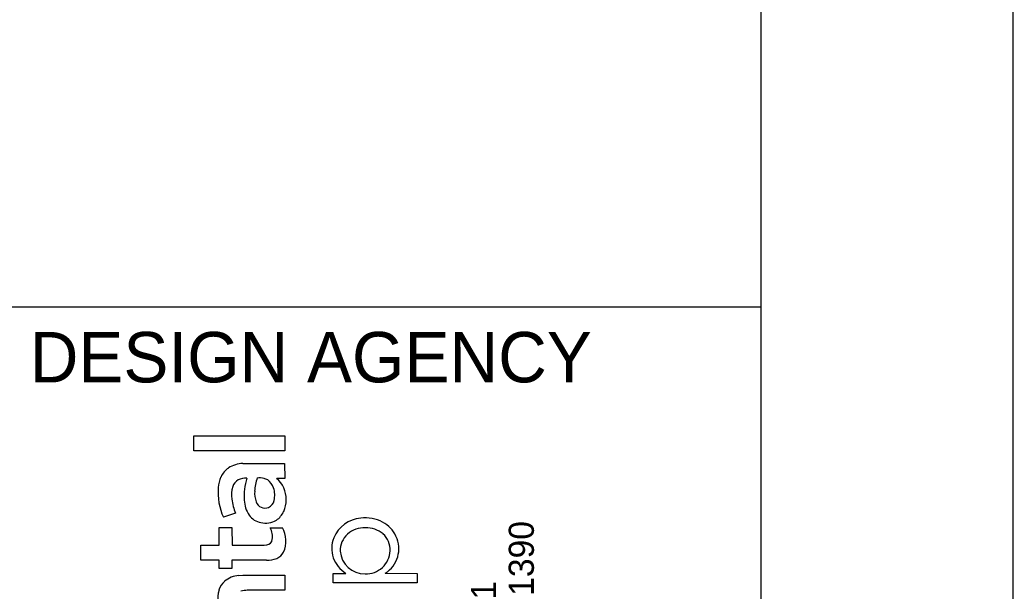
# Model space of a CAD drawing. Extents: x 0 to 63.6, y 0 to 22.
# Drawn here: x 32.03 to 34, y 4.436 to 5.569 of the extents above; entities that cross this region are included whole.
import ezdxf

# ---------------------------------------------------------------- set-up
doc = ezdxf.new("R2010")
doc.units = 0
for name, color, linetype in [('SH_Border', 7, 'Continuous'), ('SH_Cut_Line', 7, 'Continuous'), ('SH_Data', 7, 'Continuous')]:
    doc.layers.add(name, color=color, linetype=linetype)

msp = doc.modelspace()

# ---------------------------------------------------------------- linework, layer by layer
at = {"layer": 'SH_Border'}
msp.add_line((32, 5), (33.5, 5), dxfattribs=at)
msp.add_lwpolyline([(1.5, 21.5), (33.5, 21.5), (33.5, 0.5), (1.5, 0.5)], close=True, dxfattribs=at)
at = {"layer": 'SH_Cut_Line'}
msp.add_lwpolyline([(0, 0), (34, 0), (34, 22), (0, 22)], close=True, dxfattribs=at)
at = {"layer": 'SH_Data'}
for p, q in [((32.3756, 4.7141), (32.3756, 4.744)), ((32.3756, 4.744), (32.5557, 4.744)), ((32.5557, 4.744), (32.5557, 4.7141)), ((32.5557, 4.7141), (32.3756, 4.7141)), ((32.4727, 4.689), (32.5555, 4.6892)), ((32.5555, 4.6892), (32.5557, 4.6596)), ((32.5557, 4.6596), (32.5397, 4.6596)), ((32.4582, 4.5904), (32.4343, 4.5823)), ((32.4254, 4.527), (32.4255, 4.5621)), ((32.4255, 4.5621), (32.4511, 4.5621)), ((32.4511, 4.5621), (32.4512, 4.527)), ((32.527, 4.5616), (32.5511, 4.5616)), ((32.3896, 4.4972), (32.3896, 4.527)), ((32.3896, 4.527), (32.4254, 4.527)), ((32.4512, 4.527), (32.515, 4.527)), ((32.515, 4.527), (32.52, 4.5275)), ((32.4254, 4.4972), (32.3896, 4.4972)), ((32.4254, 4.4807), (32.4254, 4.4972)), ((32.5197, 4.4972), (32.4511, 4.4972)), ((32.4511, 4.4972), (32.4511, 4.4807)), ((32.4511, 4.4807), (32.4254, 4.4807)), ((32.6515, 4.4521), (32.6515, 4.4711)), ((32.6515, 4.4711), (32.6771, 4.4711)), ((32.7549, 4.4713), (32.8186, 4.4711)), ((32.8186, 4.4711), (32.8184, 4.4521)), ((32.4644, 4.4669), (32.4729, 4.4673)), ((32.4729, 4.4673), (32.5557, 4.4673)), ((32.5557, 4.4673), (32.5557, 4.4375)), ((32.8184, 4.4521), (32.6515, 4.4521)), ((32.5557, 4.4375), (32.4814, 4.4375))]:
    msp.add_line(p, q, dxfattribs=at)
msp.add_lwpolyline([(32.3756, 4.7141), (32.3756, 4.744), (32.5557, 4.744), (32.5557, 4.7141)], close=True, dxfattribs=at)
for points in [[(32.4727, 4.689), (32.5555, 4.6892), (32.5557, 4.6596)], [(32.5557, 4.6596), (32.5397, 4.6596)], [(32.4582, 4.5904), (32.4343, 4.5823)], [(32.5197, 4.4972), (32.4511, 4.4972), (32.4511, 4.4807), (32.4254, 4.4807), (32.4254, 4.4972), (32.3896, 4.4972), (32.3896, 4.527), (32.4254, 4.527), (32.4255, 4.5621), (32.4511, 4.5621), (32.4512, 4.527), (32.515, 4.527), (32.52, 4.5275)], [(32.527, 4.5616), (32.5511, 4.5616)], [(32.7549, 4.4713), (32.8186, 4.4711), (32.8184, 4.4521), (32.6515, 4.4521)], [(32.6515, 4.4521), (32.6515, 4.4711), (32.6771, 4.4711)], [(32.4644, 4.4669), (32.4729, 4.4673), (32.5557, 4.4673), (32.5557, 4.4375), (32.4814, 4.4375)]]:
    msp.add_lwpolyline(points, dxfattribs=at)
for centre, radius, start, end in [((32.4745, 4.6326), 0.0565, 91.8942, 122.6317), ((32.4745, 4.6326), 0.0565, 91.8942, 122.6317), ((32.4685, 4.6447), 0.043, 124.537, 155.6594), ((32.4685, 4.6447), 0.043, 124.537, 155.6594), ((32.4882, 4.6361), 0.0646, 155.9764, 175.3149), ((32.4882, 4.6361), 0.0646, 155.9764, 175.3149), ((32.4753, 4.6356), 0.024, 119.4252, 161.6629), ((32.4753, 4.6356), 0.024, 119.4252, 161.6629), ((32.4779, 4.6278), 0.0321, 85.3802, 116.6222), ((32.4779, 4.6278), 0.0321, 85.3802, 116.6222), ((32.5879, 4.6251), 0.1129, 162.0821, 184.5285), ((32.5879, 4.6251), 0.1129, 162.0821, 184.5285), ((32.5801, 4.6313), 0.0841, 159.8366, 178.0362), ((32.5801, 4.6313), 0.0841, 159.8366, 178.0362), ((32.5051, 4.6074), 0.053, 79.6696, 94.2322), ((32.5051, 4.6074), 0.053, 79.6696, 94.2322), ((32.5089, 4.6364), 0.0238, 56.8913, 76.2149), ((32.5089, 4.6364), 0.0238, 56.8913, 76.2149), ((32.5052, 4.6318), 0.0297, 17.5984, 55.7282), ((32.5052, 4.6318), 0.0297, 17.5984, 55.7282), ((32.5055, 4.6191), 0.0529, 358.0746, 49.762), ((32.5055, 4.6191), 0.0529, 358.0746, 49.762), ((32.5364, 4.6308), 0.113, 174.6101, 205.3899), ((32.5364, 4.6308), 0.113, 174.6101, 205.3899), ((32.5076, 4.6265), 0.0576, 163.1369, 188.1675), ((32.5076, 4.6265), 0.0576, 163.1369, 188.1675), ((32.5466, 4.6303), 0.0506, 175.5903, 199.8857), ((32.5466, 4.6303), 0.0506, 175.5903, 199.8857), ((32.4916, 4.6264), 0.0443, 345.9408, 18.9919), ((32.4916, 4.6264), 0.0443, 345.9408, 18.9919), ((32.5473, 4.6297), 0.0973, 186.7598, 203.7981), ((32.5473, 4.6297), 0.0973, 186.7598, 203.7981), ((32.5328, 4.6187), 0.0575, 182.5676, 213.7144), ((32.5328, 4.6187), 0.0575, 182.5676, 213.7144), ((32.5164, 4.6189), 0.0184, 198.2844, 293.3081), ((32.5164, 4.6189), 0.0184, 198.2844, 293.3081), ((32.5152, 4.6199), 0.0199, 295.2883, 347.4639), ((32.5152, 4.6199), 0.0199, 295.2883, 347.4639), ((32.5019, 4.6168), 0.0566, 336.016, 0.5951), ((32.5019, 4.6168), 0.0566, 336.016, 0.5951), ((32.5175, 4.6097), 0.0394, 303.4436, 336.18), ((32.5175, 4.6097), 0.0394, 303.4436, 336.18), ((32.5149, 4.6078), 0.0366, 215.0668, 259.8133), ((32.5149, 4.6078), 0.0366, 215.0668, 259.8133), ((32.5175, 4.6131), 0.0423, 257.5256, 300.882), ((32.5175, 4.6131), 0.0423, 257.5256, 300.882), ((32.7108, 4.5182), 0.0624, 93.9866, 158.3119), ((32.7108, 4.5182), 0.0624, 93.9866, 158.3119), ((32.7156, 4.5065), 0.0746, 62.6889, 97.0135), ((32.7156, 4.5065), 0.0746, 62.6889, 97.0135), ((32.7212, 4.5191), 0.0608, 25.0657, 61.9602), ((32.7212, 4.5191), 0.0608, 25.0657, 61.9602), ((32.4863, 4.542), 0.0452, 10.1545, 25.723), ((32.4863, 4.542), 0.0452, 10.1545, 25.723), ((32.4957, 4.5436), 0.0356, 351.914, 10.2059), ((32.4957, 4.5436), 0.0356, 351.914, 10.2059), ((32.503, 4.5351), 0.0549, 336.589, 28.8991), ((32.503, 4.5351), 0.0549, 336.589, 28.8991), ((32.7138, 4.5102), 0.0513, 87.8965, 131.1812), ((32.7138, 4.5102), 0.0513, 87.8965, 131.1812), ((32.7175, 4.5102), 0.0513, 49.9089, 92.0363), ((32.7175, 4.5102), 0.0513, 49.9089, 92.0363), ((32.5184, 4.54), 0.0126, 277.6142, 353.7918), ((32.5184, 4.54), 0.0126, 277.6142, 353.7918), ((32.707, 4.5202), 0.0581, 158.656, 198.171), ((32.707, 4.5202), 0.0581, 158.656, 198.171), ((32.7092, 4.5167), 0.0434, 132.3289, 182.0949), ((32.7092, 4.5167), 0.0434, 132.3289, 182.0949), ((32.7215, 4.5173), 0.0433, 358.0487, 47.9447), ((32.7215, 4.5173), 0.0433, 358.0487, 47.9447), ((32.7245, 4.52), 0.0574, 301.9776, 25.6418), ((32.7245, 4.52), 0.0574, 301.9776, 25.6418), ((32.5291, 4.5261), 0.0275, 292.6889, 332.0598), ((32.5291, 4.5261), 0.0275, 292.6889, 332.0598), ((32.7135, 4.5181), 0.0478, 183.5974, 271.7045), ((32.7135, 4.5181), 0.0478, 183.5974, 271.7045), ((32.7172, 4.518), 0.0477, 267.3149, 357.4019), ((32.7172, 4.518), 0.0477, 267.3149, 357.4019), ((32.5209, 4.5486), 0.0514, 268.6727, 291.5235), ((32.5209, 4.5486), 0.0514, 268.6727, 291.5235), ((32.7103, 4.5243), 0.0627, 200.8399, 238.0162), ((32.7103, 4.5243), 0.0627, 200.8399, 238.0162), ((32.4635, 4.4255), 0.0402, 132.2238, 161.6823), ((32.4635, 4.4255), 0.0402, 132.2238, 161.6823), ((32.4687, 4.4172), 0.0499, 94.9706, 130.2248), ((32.4687, 4.4172), 0.0499, 94.9706, 130.2248), ((32.4787, 4.4211), 0.056, 162.274, 187.7917), ((32.4787, 4.4211), 0.056, 162.274, 187.7917), ((32.4811, 4.3915), 0.046, 89.6051, 105.3303), ((32.4811, 4.3915), 0.046, 89.6051, 105.3303)]:
    msp.add_arc(centre, radius, start, end, dxfattribs=at)

# ---------------------------------------------------------------- texts
msp.add_text('DESIGN AGENCY', height=0.1, dxfattribs=at).set_placement((32.05, 4.85))
for s, p in [('800.835.1390', (33.0497, 4.1671)), ('450 GRANT ST., AKRON, OH  44311', (32.9749, 3.3374))]:
    msp.add_text(s, height=0.049846, rotation=90, dxfattribs=at).set_placement(p)

doc.saveas('drawing.dxf')
